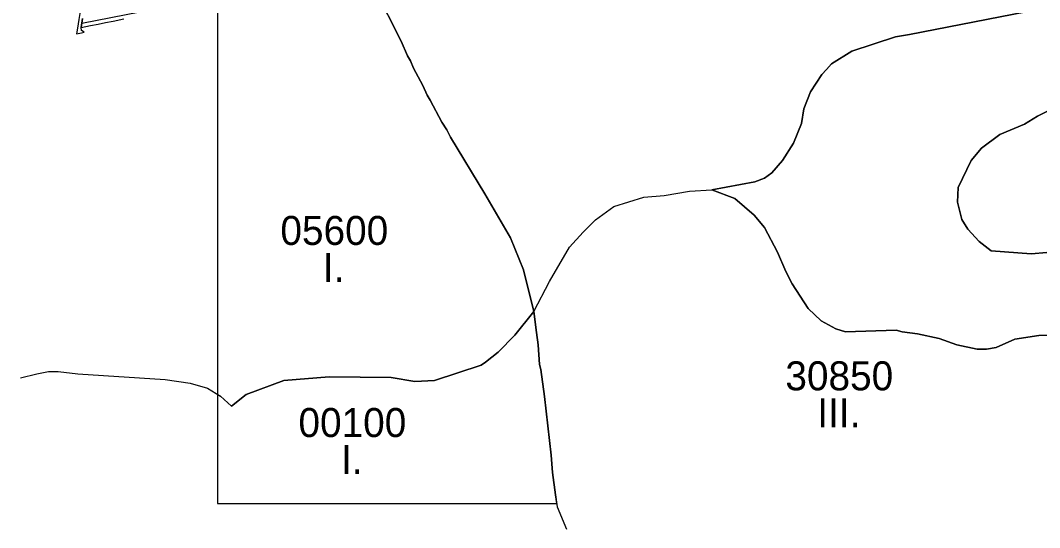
# Model space of a CAD drawing. Extents: x -555509 to -553014, y -1186753 to -1182560.
# Drawn here: x -555146 to -554443, y -1185899 to -1185549 of the extents above; entities that cross this region are included whole.
import ezdxf

# ---------------------------------------------------------------- set-up
doc = ezdxf.new("R2010")
doc.units = 0
for name, color, linetype in [('I_2_Leg_HV', 7, 'Continuous'), ('LEG_6_ZPF', 7, 'Continuous'), ('Level 29', 7, 'Continuous'), ('pěší_tr', 7, 'Continuous'), ('zatrubnene_toky', 7, 'Continuous'), ('ZPF_I_TR_OCHRANY', 7, 'Continuous')]:
    doc.layers.add(name, color=color, linetype=linetype)

msp = doc.modelspace()

# ---------------------------------------------------------------- linework, layer by layer
at = {"layer": 'I_2_Leg_HV'}
msp.add_lwpolyline([(-555102.7, -1185547.85), (-555103.67, -1185553.95), (-555097.15, -1185552.66), (-555092.01, -1185551.63), (-555086.88, -1185550.61), (-555081.55, -1185549.55), (-555074.12, -1185548.07)], dxfattribs=at)
at = {"layer": 'LEG_6_ZPF'}
for p, q in [((-554542.06, -1185560.5), (-554572.19, -1185570.25)), ((-554606.94, -1185620.25), (-554612.44, -1185633.75)), ((-554639.12, -1185660.5), (-554668.81, -1185666)), ((-554499.25, -1185674.5), (-554498.81, -1185664.38)), ((-554496.25, -1185686.38), (-554499.25, -1185674.5)), ((-554492.06, -1185693.13), (-554496.25, -1185686.38)), ((-554484.38, -1185701.63), (-554492.06, -1185693.13)), ((-554475.94, -1185708), (-554484.38, -1185701.63)), ((-554448.38, -1185710.13), (-554475.94, -1185708)), ((-554437.75, -1185709.25), (-554448.38, -1185710.13))]:
    msp.add_line(p, q, dxfattribs=at)
for points in [[(-554434.38, -1185539.63), (-554532.31, -1185558.75), (-554542.06, -1185560.5)], [(-554572.19, -1185570.25), (-554586.19, -1185579.13), (-554589.56, -1185582.88)], [(-554589.56, -1185582.88), (-554592.94, -1185586.38), (-554600.56, -1185598.25)], [(-554600.56, -1185598.25), (-554605.25, -1185610), (-554606.94, -1185620.25)], [(-554470, -1185627.88), (-554453, -1185620.63), (-554444.12, -1185615.13), (-554433.94, -1185610)], [(-554498.81, -1185664.38), (-554489.94, -1185645.62), (-554482.69, -1185637.25), (-554470, -1185627.88)], [(-554612.44, -1185633.75), (-554620.06, -1185645.62), (-554627.31, -1185654.12)], [(-554627.31, -1185654.12), (-554632.38, -1185658), (-554639.12, -1185660.5)], [(-554668.81, -1185666), (-554652.75, -1185672), (-554639.56, -1185683.38), (-554632.38, -1185691.88), (-554623.5, -1185708.88), (-554617.56, -1185722.38), (-554613.31, -1185730.88), (-554602.25, -1185747.88), (-554593.38, -1185756.38), (-554583.19, -1185761.88), (-554576.44, -1185764), (-554541.62, -1185762.75), (-554537.38, -1185764), (-554526.81, -1185765.25), (-554511.94, -1185768.62), (-554499.69, -1185772.88), (-554485.69, -1185775.88), (-554479.31, -1185775.88), (-554472.56, -1185774.63), (-554459.81, -1185769), (-554443.25, -1185766.5), (-554432.25, -1185766.13)]]:
    msp.add_lwpolyline(points, dxfattribs=at)
at = {"layer": 'Level 29'}
for points in [[(-554668.81, -1185666), (-554639.12, -1185660.5), (-554632.38, -1185658), (-554627.31, -1185654.12), (-554620.06, -1185645.62), (-554612.44, -1185633.75), (-554606.94, -1185620.25), (-554605.25, -1185610), (-554600.56, -1185598.25), (-554592.94, -1185586.38), (-554589.56, -1185582.88), (-554586.19, -1185579.13), (-554572.19, -1185570.25), (-554542.06, -1185560.5), (-554532.31, -1185558.75), (-554434.38, -1185539.63), (-554415.75, -1185534.63), (-554383.06, -1185521), (-554358.88, -1185506.63), (-554332.19, -1185482.88)], [(-554909.62, -1185507.5), (-554902.88, -1185524.38), (-554901.19, -1185527.38), (-554882.94, -1185563.38), (-554878.69, -1185573.62), (-554876.56, -1185577), (-554874.44, -1185582.12), (-554868.12, -1185594), (-554865.12, -1185600.75), (-554863, -1185604.13), (-554854.94, -1185619.38), (-554851.56, -1185624.5), (-554849, -1185629.62), (-554825.25, -1185668.63), (-554807.5, -1185699.12), (-554798.56, -1185721.13), (-554791.38, -1185750)], [(-554433.94, -1185610), (-554444.12, -1185615.13), (-554453, -1185620.63), (-554470, -1185627.88), (-554482.69, -1185637.25), (-554489.94, -1185645.62), (-554498.81, -1185664.38), (-554499.25, -1185674.5), (-554496.25, -1185686.38), (-554492.06, -1185693.13), (-554484.38, -1185701.63), (-554475.94, -1185708), (-554448.38, -1185710.13), (-554437.75, -1185709.25)], [(-554791.38, -1185750), (-554780.75, -1185729.25), (-554766.75, -1185705.5), (-554757.44, -1185695.25), (-554748.94, -1185686.75), (-554736.25, -1185677.5), (-554715.5, -1185671.12), (-554701.5, -1185669.88), (-554684.12, -1185666.88), (-554668.81, -1185666)], [(-554432.25, -1185766.13), (-554443.25, -1185766.5), (-554459.81, -1185769), (-554472.56, -1185774.63), (-554479.31, -1185775.88), (-554485.69, -1185775.88), (-554499.69, -1185772.88), (-554511.94, -1185768.62), (-554526.81, -1185765.25), (-554537.38, -1185764), (-554541.62, -1185762.75), (-554576.44, -1185764), (-554583.19, -1185761.88), (-554593.38, -1185756.38), (-554602.25, -1185747.88), (-554613.31, -1185730.88), (-554617.56, -1185722.38), (-554623.5, -1185708.88), (-554632.38, -1185691.88), (-554639.56, -1185683.38), (-554652.75, -1185672), (-554668.81, -1185666)], [(-555145.56, -1185795.73), (-555134.31, -1185793), (-555126.25, -1185791.25), (-555119.5, -1185791.25), (-555105.94, -1185793), (-555045.75, -1185796.75), (-555028.38, -1185799.38), (-555016.5, -1185802.75), (-555007.62, -1185808.25), (-555000, -1185815.25), (-554989.81, -1185807.25), (-554963.94, -1185797.5), (-554932.56, -1185794.88), (-554889.75, -1185795.38), (-554873.62, -1185798.25), (-554860.06, -1185797.5), (-554827.81, -1185786.88), (-554824.88, -1185784.75), (-554815.94, -1185778), (-554804.5, -1185766.13), (-554791.38, -1185750)], [(-554791.38, -1185750), (-554789.69, -1185764.38), (-554788.38, -1185772.88), (-554787.56, -1185786.5), (-554786.69, -1185789.88), (-554784.12, -1185808.5), (-554779.5, -1185849.12), (-554778.62, -1185861), (-554776.5, -1185876.38), (-554775.25, -1185884.75), (-554768.88, -1185900.13)]]:
    msp.add_lwpolyline(points, dxfattribs=at)
at = {"layer": 'pěší_tr'}
for points in [[(-555038.22, -1185140.93), (-555040.43, -1185171.71), (-555049.1, -1185240.01), (-555058.64, -1185297.02), (-555070.07, -1185365.86), (-555076.4, -1185399.4), (-555083.43, -1185437.16), (-555086.38, -1185454.6), (-555089.38, -1185463.99), (-555101.61, -1185526.2), (-555105.26, -1185548.34), (-555106.28, -1185554.52), (-555106.91, -1185558.36)], [(-555101.62, -1185557.29), (-555103.31, -1185555.94), (-555103.67, -1185553.95), (-555102.7, -1185547.85)], [(-555106.91, -1185558.36), (-555103.5, -1185557.7)], [(-555103.5, -1185557.7), (-555101.62, -1185557.29)]]:
    msp.add_lwpolyline(points, dxfattribs=at)
at = {"layer": 'zatrubnene_toky'}
msp.add_lwpolyline([(-554855.15, -1185503.23), (-554886.23, -1185508.85), (-554936.81, -1185519.03), (-554993.89, -1185530.31), (-555043.24, -1185539.52), (-555103.24, -1185551.24)], dxfattribs=at)
at = {"layer": 'ZPF_I_TR_OCHRANY'}
for p, q in [((-555009.53, -1185498.24), (-555009.53, -1185807.07)), ((-554874.44, -1185582.12), (-554868.12, -1185594)), ((-554868.12, -1185594), (-554865.12, -1185600.75)), ((-554854.94, -1185619.38), (-554851.56, -1185624.5)), ((-554851.56, -1185624.5), (-554849, -1185629.62)), ((-554849, -1185629.62), (-554825.25, -1185668.63)), ((-554825.25, -1185668.63), (-554807.5, -1185699.12)), ((-554963.94, -1185797.5), (-554989.81, -1185807.25)), ((-554873.62, -1185798.25), (-554889.75, -1185795.38)), ((-554860.06, -1185797.5), (-554873.62, -1185798.25)), ((-555007.62, -1185808.25), (-555009.53, -1185807.07)), ((-555009.53, -1185807.07), (-555009.53, -1185882.32)), ((-555000, -1185815.25), (-555007.62, -1185808.25)), ((-554989.81, -1185807.25), (-555000, -1185815.25)), ((-555009.53, -1185882.32), (-554775.61, -1185882.32))]:
    msp.add_line(p, q, dxfattribs=at)
for points in [[(-554668.81, -1185666), (-554639.12, -1185660.5), (-554632.38, -1185658), (-554627.31, -1185654.12), (-554620.06, -1185645.62), (-554612.44, -1185633.75), (-554606.94, -1185620.25), (-554605.25, -1185610), (-554600.56, -1185598.25), (-554592.94, -1185586.38), (-554589.56, -1185582.88), (-554586.19, -1185579.13), (-554572.19, -1185570.25), (-554542.06, -1185560.5), (-554532.31, -1185558.75), (-554434.38, -1185539.63), (-554415.75, -1185534.63), (-554383.06, -1185521), (-554358.88, -1185506.63), (-554332.19, -1185482.88)], [(-554791.38, -1185750), (-554798.56, -1185721.13), (-554807.5, -1185699.12), (-554825.25, -1185668.63), (-554849, -1185629.62), (-554851.56, -1185624.5), (-554854.94, -1185619.38), (-554863, -1185604.13), (-554865.12, -1185600.75), (-554868.12, -1185594), (-554874.44, -1185582.12), (-554876.56, -1185577), (-554878.69, -1185573.62), (-554882.94, -1185563.38), (-554901.19, -1185527.38), (-554902.88, -1185524.38), (-554909.62, -1185507.5)], [(-554909.62, -1185507.5), (-554902.88, -1185524.38), (-554901.19, -1185527.38), (-554882.94, -1185563.38), (-554878.69, -1185573.62), (-554876.56, -1185577), (-554874.44, -1185582.12)], [(-554865.12, -1185600.75), (-554863, -1185604.13), (-554854.94, -1185619.38)], [(-554433.94, -1185610), (-554444.12, -1185615.13), (-554453, -1185620.63), (-554470, -1185627.88), (-554482.69, -1185637.25), (-554489.94, -1185645.62), (-554498.81, -1185664.38), (-554499.25, -1185674.5), (-554496.25, -1185686.38), (-554492.06, -1185693.13), (-554484.38, -1185701.63), (-554475.94, -1185708), (-554448.38, -1185710.13), (-554437.75, -1185709.25)], [(-554791.38, -1185750), (-554780.75, -1185729.25), (-554766.75, -1185705.5), (-554757.44, -1185695.25), (-554748.94, -1185686.75), (-554736.25, -1185677.5), (-554715.5, -1185671.12), (-554701.5, -1185669.88), (-554684.12, -1185666.88), (-554668.81, -1185666)], [(-554807.5, -1185699.12), (-554798.56, -1185721.13), (-554791.38, -1185750)], [(-555009.53, -1185807.07), (-555007.62, -1185808.25), (-555000, -1185815.25), (-554989.81, -1185807.25), (-554963.94, -1185797.5), (-554932.56, -1185794.88), (-554889.75, -1185795.38), (-554873.62, -1185798.25), (-554860.06, -1185797.5), (-554827.81, -1185786.88), (-554824.88, -1185784.75), (-554815.94, -1185778), (-554804.5, -1185766.13), (-554791.38, -1185750)], [(-554791.38, -1185750), (-554804.5, -1185766.13), (-554815.94, -1185778), (-554824.88, -1185784.75), (-554827.81, -1185786.88), (-554860.06, -1185797.5)], [(-554775.61, -1185882.32), (-554776.5, -1185876.38), (-554778.62, -1185861), (-554779.5, -1185849.12), (-554784.12, -1185808.5), (-554786.69, -1185789.88), (-554787.56, -1185786.5), (-554788.38, -1185772.88), (-554789.69, -1185764.38), (-554791.38, -1185750)], [(-554889.75, -1185795.38), (-554932.56, -1185794.88), (-554963.94, -1185797.5)]]:
    msp.add_lwpolyline(points, dxfattribs=at)

# ---------------------------------------------------------------- texts
at = {"layer": 'Level 29'}
for s, p in [('05600', (-554966.23, -1185703.98)), ('I.', (-554936.92, -1185729.43)), ('30850', (-554618, -1185804.28)), ('III.', (-554595.96, -1185829.74)), ('00100', (-554953.77, -1185836.5)), ('I.', (-554924.46, -1185861.96))]:
    msp.add_text(s, height=20, dxfattribs=at).set_placement(p)

doc.saveas('drawing.dxf')
